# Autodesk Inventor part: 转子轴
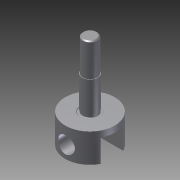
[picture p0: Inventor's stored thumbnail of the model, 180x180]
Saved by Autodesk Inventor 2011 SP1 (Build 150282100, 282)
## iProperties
Created: 2013-12
Part Number: 转子轴
Document SubType Name: Modeling
Designer: Administrator
Density: 1 g/cm^3
Author: Administrator
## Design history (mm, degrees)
sketch "草图1"
  geometry: C1 r 24 at (0, 0); 1 further point
  constraints: 1 centre point, 1 coincident
  dimensions: "d0" = 48 diameter of C1
extrude "拉伸1" new body sketch "草图1" distance "d1" = 28; taper "d2" = 0 deg
sketch "草图2"
  geometry: C1 r 24 at (0, 0) reference; C2 r 7.5 at (0, 0)
  constraints: 1 centre point, 1 coincident
  dimensions: "d3" = 15 diameter of C2
extrude "拉伸2" join sketch "草图2" distance "d4" = 32; taper "d5" = 0 deg
sketch "草图3"
  geometry: C1 r 7.5 at (0, 0) reference; C2 r 7 at (0, 0)
  constraints: 1 centre point, 1 coincident
  dimensions: "d6" = 14 diameter of C2
extrude "拉伸3" join sketch "草图3" distance "d7" = 32; taper "d8" = 0 deg
chamfer "倒角1" distance "d9" = 1; stored, may be unused: second distance "d10" = 2, angle "d11" = 45 deg
node "工作平面1"
sketch "草图4"
  geometry: 2 further points
  dimensions: "d13" = 12 distance of point (0, 0) point (0, 12)
hole "Hole1" sketch "草图4" at (0, 12) diameter "d14" = 16; stored, may be unused: countersink angle "d18" = 90 deg, drill point angle "d20" = 118 deg; dims "d15" = 6, "d16" = 4, "d17" = 2, "d19" = 8
sketch "草图5"
  geometry: L1 (-24, -11)-(24, -11); L2 (24, -11)-(24, 11); L3 (24, 11)-(-24, 11); L4 (-24, 11)-(-24, -11); C1 r 24 at (0, 0) reference; 2 further points
  constraints: 8 end point, 2 midpoint, 2 parallel, 1 horizontal, 1 horizontal alignment, 1 perpendicular, 1 vertical alignment
  dimensions: "d21" = 22 distance of L3.end L1.start; "d22" = 48 distance of L2.end L3.end
extrude "拉伸4" cut sketch "草图5" distance "d23" = 22; taper "d24" = 0 deg
sketch "草图6"
  geometry: L1 (-24, 28)-(24, 28) reference; L2 (-7.5, 28)-(-7.5, 60) reference; L3 (7.5, 28)-(7.5, 60) reference; L4 (7.5, 30)-(7, 29.5); L5 (7, 29.5)-(7, 28); L6 (7.5, 27.5)-(9, 27.5); L7 (9, 27.5)-(9.5, 28); L8 (0, -18.4)-(0, 110.4) reference; A1 r 0.5 centre (7.5, 28) between (7, 28) and (7.5, 27.5); 1 further point
  constraints: 8 end point, 2 parallel, 2 point on circle, 2 point on line, 2 tangent, 1 centre point, 1 perpendicular
  dimensions: "d25" = 45 deg angle of L1 L7; "d26" = 45 deg angle of L4 L3 (derived); "d27" = 0.5 radius of A1; "d28" = 0.5 distance between parallel lines of L3 L5; "d29" = 0.5 distance between parallel lines of L1 L6; "d30" = 2 horizontal distance of L4.start L7.end; "d31" = 2 distance from line of L3 L7.end
revolve "旋转1" sketch "草图6" stored, may be unused: angle "d32" = 90 deg
node "实体1"
other parameters: "d12" = -24
